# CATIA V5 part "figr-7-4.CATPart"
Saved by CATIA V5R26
Part number: Part1
Bounding box of the stored display mesh (mm): x -20 to 20, y -95 to 0, z 0 to 40
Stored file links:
  D:\_Deepak\CATIA\CATIA V5-6R2016_Deepak\Resources\Part files\Partfiles\c07_catia_v5_6r2016_prt\figr-7-4.CATPart
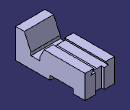
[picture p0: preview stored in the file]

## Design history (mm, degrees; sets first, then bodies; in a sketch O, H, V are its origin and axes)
Body1 (main body)
  Sketch1 on yz-plane, origin (0, 0, 0), H (0, 1, 0), V (0, 0, 1)
    line L1 (0, 0) -> (-16, 0)
    line L2 (-16, 0) -> (-16, 6)
    line L3 (-16, 6) -> (-48, 6)
    line L4 (-48, 6) -> (-48, 0)
    point P4 (-48, 0)
    line L5 (-48, 0) -> (-95, 0)
    line L6 (-95, 0) -> (-95, 40)
    line L7 (-95, 40) -> (-83, 40)
    line L8 (-83, 40) -> (-74, 20)
    line L9 (-74, 20) -> (-74, 16)
    line L10 (-74, 16) -> (-62, 16)
    line L11 (-62, 16) -> (-62, 20)
    line L12 (-62, 20) -> (-56, 32)
    line L13 (-56, 32) -> (0, 32)
    line L14 (0, 32) -> (0, 0)
    length L1 = 16
    length L3 = 32
    length L13 = 56
    distance L14 L6 = 95
    length L14 = 32
    length L6 = 40
    length L12 H = 6
    length L10 = 12
    length L7 = 12
    length L9 = 4
    length L2 = 6
    distance L10 L5 = 16
    length L12 V = 12
    horizontal: L1 H, L3 H, L5 H, L7 H, L10 H, L13 H
    vertical: L2 V, L4 V, L6 V, L9 V, L11 V, L14 V
    coincidence: P4 H
  Pad1: profile Sketch1, direction (1, 0, 0), length 20, mirrored extent
  Sketch2 on face of Pad1, origin (0, 0, 0), H (-1, 0, 0), V (0, 0, 1)
    axis line L1 (0, 0) -> (0, 40.9766)
    point P2 (0, 32)
    line L2 (0, 32) -> (-8, 32)
    point P3 (-8, 32)
    line L3 (-8, 32) -> (-12, 26)
    point P4 (-12, 26)
    line L4 (-12, 26) -> (0, 26)
    point P5 (0, 26)
    reference projected line E1 (-20, 32) -> (20, 32) from edge [face of Pad1 | face of Pad1]
    point P6 (0, 32)
    point P7 (8, 32)
    point P8 (12, 26)
    point P9 (0, 26)
    line L5 (0, 32) -> (8, 32)
    line L6 (8, 32) -> (12, 26)
    line L7 (12, 26) -> (0, 26)
    reference projected line E2 (-20, 0) -> (-20, 32) from edge [face of Pad1 | face of Pad1]
    reference projected line E3 (-20, 20) -> (-20, 40) from edge [face of Pad1 | face of Pad1]
    distance P4 E2 = 8
    length L3 V = 6
    distance P3 E3 = 12
    vertical: L1 V
    coincidence: P2 L1, P5 L1, L2 E1, P2 P6, P5 P9
    horizontal: L2 H, L4 H
    symmetry: P2 P6 L1, P3 P7 L1, P4 P8 L1, P5 P9 L1, L2 L5 L1, L3 L6 L1, L4 L7 L1
  Pocket1: profile Sketch2, direction (0, -1, 0), through (limit type 6)
  Sketch3 on face of Pad1, origin (0, 0, 0), H (-1, 0, 0), V (0, 0, 1)
    line L1 (-6, 0) -> (6, 0)
    line L2 (6, 0) -> (6, 26)
    line L3 (6, 26) -> (-6, 26)
    line L4 (-6, 26) -> (-6, 0)
    reference projected line E1 (-12, 26) -> (0, 26) from edge [face of Pad1 | face of Pocket1]
    length L1 = 12
    horizontal: L1 H, L3 H
    vertical: L2 V, L4 V
    midpoint: O L1
    coincidence: L3 E1
  Pocket2: profile Sketch3, direction (0, -1, 0), length 4
  Sketch4 "Sketch.4" on face of Pad1, origin (0, 0, 40), H (1, 0, 0), V (0, 1, 0)
    line L1 (-12.5, -95) -> (12.5, -95)
    line L2 (12.5, -95) -> (12.5, -92)
    line L3 (12.5, -92) -> (-12.5, -92)
    line L4 (-12.5, -92) -> (-12.5, -95)
    reference projected line E1 (-20, -95) -> (20, -95) from edge [face of Pad1 | face of Pad1]
    axis line L5 (0, 0) -> (0, -95)
    point P5 (0, -95)
    length L1 = 25
    length L2 = 3
    horizontal: L1 H, L3 H
    vertical: L2 V, L4 V, L5 V
    coincidence: L1 E1
    midpoint: P5 L1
